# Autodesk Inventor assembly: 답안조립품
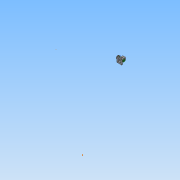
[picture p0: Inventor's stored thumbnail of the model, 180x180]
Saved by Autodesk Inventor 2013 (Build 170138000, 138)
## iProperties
Created: 2016-02
Part Number: 답안조립품
Document SubType Name: Assembly
Designer: Administrator
Author: Administrator
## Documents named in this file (16)
- C:\Users\Administrator\Desktop\460212V1018\답안조립품.iam
- C:\Users\Administrator\Desktop\460212V1018\본체.ipt
- C:\Users\Administrator\Desktop\460212V1018\V벨트풀리.ipt
- C:\Users\Administrator\Desktop\460212V1018\고정핀 1.2 x 10.ipt
- C:\Users\Administrator\Desktop\460212V1018\뒤커버.ipt
- C:\Users\Administrator\Desktop\460212V1018\링크.ipt
- C:\Users\Administrator\Desktop\460212V1018\멈춤나사 M3x8.ipt
- C:\Users\Administrator\Desktop\460212V1018\베어링 12 x 32 x 10.ipt
- C:\Users\Administrator\Desktop\460212V1018\볼트 M4 x 12.ipt
- C:\Users\Administrator\Desktop\460212V1018\부시.ipt
- C:\Users\Administrator\Desktop\460212V1018\슬라이드.ipt
- C:\Users\Administrator\Desktop\460212V1018\앞커버.ipt
- C:\Users\Administrator\Desktop\460212V1018\오일실 12 25 7.ipt
- C:\Users\Administrator\Desktop\460212V1018\키 4 x 4 x 10.ipt
- C:\Users\Administrator\Desktop\460212V1018\편심축.ipt
- C:\Users\Administrator\Desktop\460212V1018\핀 5 x 18.ipt
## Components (11 placed, 4 different names)
1. V벨트풀리:1 — 플러쉬:1
2. 고정핀 1.2 x 10:1 — 각도:1, 플러쉬:3
3. 핀 5 x 18:1 — 각도:1, 플러쉬:3
4. ISO 4762 M4 x 12:1
5. ISO 4762 M4 x 12:2
6. ISO 4762 M4 x 12:3
7. ISO 4762 M4 x 12:4
8. ISO 4762 M4 x 12:5
9. ISO 4762 M4 x 12:6
10. ISO 4762 M4 x 12:7
11. ISO 4762 M4 x 12:8
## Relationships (3: Flush 2, Angle 1)
- 플러쉬:1 [Flush]: V벨트풀리:1
- 각도:1 [Angle]: 고정핀 1.2 x 10:1 ↔ 핀 5 x 18:1
- 플러쉬:3 [Flush]: 고정핀 1.2 x 10:1 ↔ 핀 5 x 18:1
